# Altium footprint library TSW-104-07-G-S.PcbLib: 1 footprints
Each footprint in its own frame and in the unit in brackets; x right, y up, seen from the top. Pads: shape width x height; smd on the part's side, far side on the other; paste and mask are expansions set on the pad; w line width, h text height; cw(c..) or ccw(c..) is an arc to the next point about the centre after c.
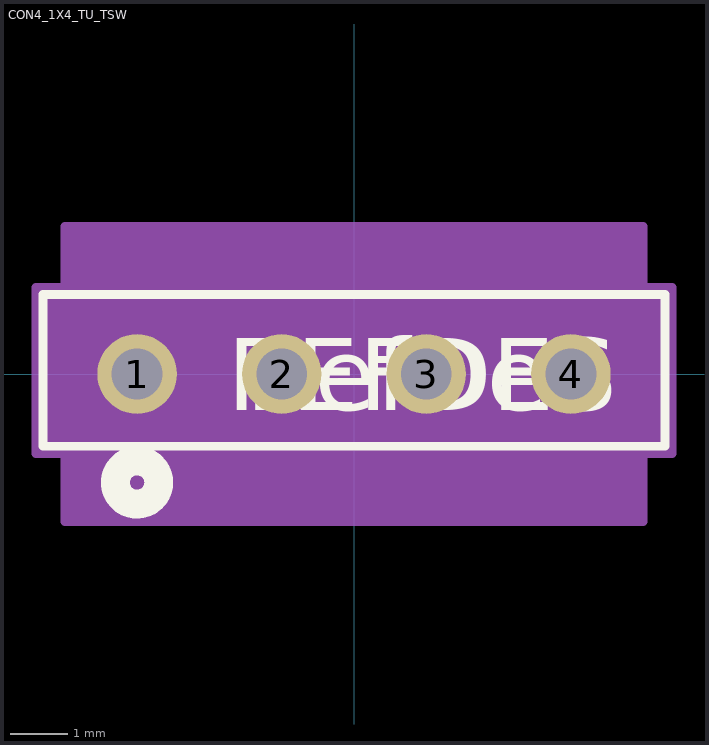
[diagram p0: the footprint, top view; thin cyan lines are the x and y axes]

## CON4_1X4_TU_TSW [mil]
pads (4):
  round 55 / inner round 60 / far side round 55 hole 35 paste-27.5 mask+0: 1(-150,0) 2(-50,0) 3(50,0) 4(150,0)
Top Overlay:
  circle w20: c-150,-75 r15
  lines w6: -215,-50 215,-50 215,55 -215,55 -215,-50
  text "RefDes" at -75,-25 h50
  text "REFDES" at -87.5,-25 h50
Bottom Overlay:
  circle w20: c-150,-75 r15
Mechanical 13:
  circle w0: c-150,0 r10
  lines w1: -210,-45 210,-45 210,50 -210,50 -210,-45
  text "RefDes2" at -87.5,-25 h50
Mechanical 15:
  region: 220,60 200,60 200,102 -200,102 -200,60 -220,60 -220,-55 -200,-55 -200,-102 200,-102 200,-55 220,-55
  lines w6: -220,-55 -220,60 -200,60 -200,102 200,102 200,60 220,60 220,-55 200,-55 200,-102 -200,-102 -200,-55 -220,-55
3D body "CON4_1X4_TU_TSW.step": height 500, standoff -200, extent -200,-50 200,50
